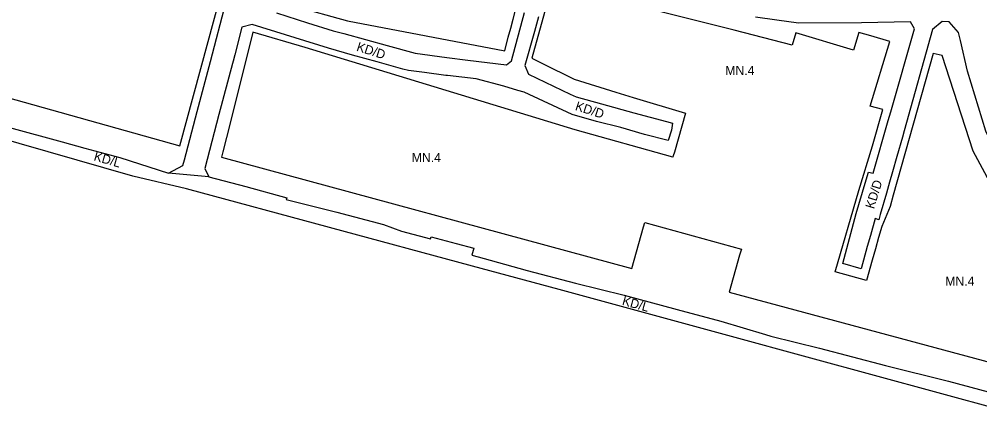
# Model space of a CAD drawing. Extents: x 7417499 to 7419078, y 5548267 to 5548936.
# Drawn here: x 7418035 to 7418562, y 5548333 to 5548556 of the extents above; entities that cross this region are included whole.
import ezdxf

# ---------------------------------------------------------------- set-up
doc = ezdxf.new("R2010")
doc.units = 0
for name, color, linetype in [('linie_rozgraniczajace', 7, 'Continuous'), ('linie_zabudowy_nieprzekraczalne', 7, 'Continuous'), ('oznaczenia_przeznaczen', 7, 'Continuous')]:
    doc.layers.add(name, color=color, linetype=linetype)

msp = doc.modelspace()

# ---------------------------------------------------------------- linework, layer by layer
at = {"layer": 'linie_rozgraniczajace'}
for p, q in [((7418140.18, 5548532.38), (7418148.83, 5548565.16)), ((7418176.38, 5548558.95), (7418193.33, 5548553.59)), ((7418305.05, 5548532.66), (7418312.27, 5548559.22)), ((7418320.01, 5548556.82), (7418317.71, 5548548.86)), ((7418450.55, 5548555.04), (7418438.88, 5548556.71)), ((7418193.33, 5548553.59), (7418207.37, 5548549.17)), ((7418462.43, 5548553.41), (7418450.55, 5548555.04)), ((7418496.94, 5548553.61), (7418462.43, 5548553.41)), ((7418523.79, 5548554.05), (7418496.94, 5548553.61)), ((7418541.11, 5548554.28), (7418535.82, 5548549.91)), ((7418544.87, 5548554.11), (7418541.11, 5548554.28)), ((7418549.91, 5548548.26), (7418544.87, 5548554.11)), ((7418207.37, 5548549.17), (7418213.38, 5548547.69)), ((7418213.38, 5548547.69), (7418236.98, 5548541.18)), ((7418317.71, 5548548.86), (7418312.52, 5548530.15)), ((7418551.14, 5548543.93), (7418549.91, 5548548.26)), ((7418236.98, 5548541.18), (7418252.37, 5548536.92)), ((7418554.84, 5548526.98), (7418551.14, 5548543.93)), ((7418218.11, 5548535.89), (7418204.87, 5548539.59)), ((7418231.55, 5548532.12), (7418218.11, 5548535.89)), ((7418252.37, 5548536.92), (7418269.64, 5548534.56)), ((7418132.97, 5548504.91), (7418140.18, 5548532.38)), ((7418152.36, 5548531.24), (7418144.82, 5548503.35)), ((7418152.67, 5548532.45), (7418152.36, 5548531.24)), ((7418269.64, 5548534.56), (7418281.29, 5548533.12)), ((7418281.29, 5548533.12), (7418302.4, 5548530.51)), ((7418302.4, 5548530.51), (7418305.05, 5548532.66)), ((7418312.52, 5548530.15), (7418314.48, 5548525.43)), ((7418257.44, 5548526.26), (7418248.65, 5548527.34)), ((7418314.48, 5548525.43), (7418337.2, 5548514.42)), ((7418308.63, 5548516.52), (7418300.88, 5548518.75)), ((7418312.08, 5548515.52), (7418308.63, 5548516.52)), ((7418338.39, 5548503.23), (7418312.08, 5548515.52)), ((7418125.98, 5548478.36), (7418132.97, 5548504.91)), ((7418144.82, 5548503.35), (7418137.13, 5548473.69)), ((7418511.48, 5548499.97), (7418512.84, 5548504.75)), ((7418351.66, 5548499.46), (7418338.39, 5548503.23)), ((7418365.02, 5548496.13), (7418351.66, 5548499.46)), ((7418393.36, 5548498.51), (7418392.71, 5548494.63)), ((7418377.94, 5548492.37), (7418365.02, 5548496.13)), ((7418392.71, 5548494.63), (7418391, 5548488.93)), ((7418391, 5548488.93), (7418377.94, 5548492.37)), ((7418519.33, 5548490.87), (7418516.3, 5548480.31)), ((7418516.3, 5548480.31), (7418513.88, 5548471.88)), ((7418137.13, 5548473.69), (7418139.29, 5548469.13)), ((7418513.88, 5548471.88), (7418512.25, 5548466.18)), ((7418127.14, 5548462.45), (7418097.71, 5548469.54)), ((7418139.29, 5548469.13), (7418159.56, 5548463.75)), ((7418159.56, 5548463.75), (7418182.03, 5548457.58)), ((7418512.25, 5548466.18), (7418510.51, 5548460.13)), ((7418182.03, 5548457.58), (7418181.71, 5548456.69)), ((7418510.51, 5548460.13), (7418507.17, 5548448.48)), ((7418506.32, 5548445.51), (7418504.31, 5548446.18)), ((7418507.17, 5548448.48), (7418506.32, 5548445.51)), ((7418235.04, 5548442.95), (7418244.97, 5548439.29)), ((7418244.97, 5548439.29), (7418260.77, 5548435.13)), ((7418260.77, 5548435.13), (7418261.12, 5548436.25)), ((7418284.54, 5548429.93), (7418283.4, 5548426.1)), ((7418500.05, 5548430.86), (7418496.66, 5548418.66)), ((7418283.4, 5548426.1), (7418286.84, 5548425.18)), ((7418286.84, 5548425.18), (7418293.42, 5548423.3)), ((7418293.42, 5548423.3), (7418313.65, 5548417.75)), ((7418313.65, 5548417.75), (7418340.2, 5548410.72)), ((7418340.2, 5548410.72), (7418366.85, 5548404.19)), ((7418469.14, 5548369.7), (7418423.6, 5548382.15)), ((7418473.93, 5548375.07), (7418509.97, 5548365.69)), ((7418603.32, 5548333.1), (7418469.14, 5548369.7)), ((7418509.97, 5548365.69), (7418544.48, 5548357.03)), ((7418544.48, 5548357.03), (7418544.48, 5548357.03)), ((7418544.48, 5548357.03), (7418597.6, 5548342.57))]:
    msp.add_line(p, q, dxfattribs=at)
for points in [[(7418157.51, 5548551.22), (7418153.56, 5548535.92), (7418152.67, 5548532.45)], [(7418204.87, 5548539.59), (7418163.07, 5548552.63), (7418157.51, 5548551.22)], [(7418512.84, 5548504.75), (7418525.89, 5548550.28), (7418523.79, 5548554.05)], [(7418535.82, 5548549.91), (7418520.3, 5548494.35), (7418519.33, 5548490.87)], [(7418248.65, 5548527.34), (7418245.58, 5548528.22), (7418231.55, 5548532.12)], [(7418300.88, 5548518.75), (7418285.78, 5548522.89), (7418269.99, 5548524.6), (7418269.2, 5548524.65), (7418257.44, 5548526.26)], [(7418574.08, 5548474.86), (7418564.97, 5548494.08), (7418554.84, 5548526.98)], [(7418337.2, 5548514.42), (7418340.65, 5548512.9), (7418354.43, 5548509.12), (7418372.2, 5548504.24), (7418389.97, 5548499.35), (7418393.36, 5548498.51)], [(7417998.31, 5548508.7), (7418000.68, 5548504.27), (7418030.07, 5548496.11), (7418059.01, 5548488.22), (7418071.43, 5548484.83), (7418090.51, 5548479.62)], [(7418097.71, 5548469.54), (7417988.86, 5548500.74)], [(7418500.74, 5548471.66), (7418503.19, 5548471.05), (7418511.48, 5548499.97)], [(7418090.51, 5548479.62), (7418117.24, 5548471.13)], [(7418117.24, 5548471.13), (7418125.11, 5548475.33), (7418125.98, 5548478.36)], [(7418139.29, 5548469.13), (7418117.24, 5548471.13)], [(7418139.29, 5548469.13), (7418117.24, 5548471.13)], [(7418493.97, 5548448.92), (7418498.82, 5548465.55), (7418500.74, 5548471.66)], [(7418423.6, 5548382.15), (7418331.2, 5548407.22), (7418283.86, 5548420.06), (7418127.14, 5548462.45)], [(7418181.71, 5548456.69), (7418209.43, 5548449.76), (7418235.04, 5548442.95)], [(7418496.66, 5548418.66), (7418486.56, 5548421.48), (7418493.97, 5548448.92)], [(7418504.31, 5548446.18), (7418501.75, 5548436.93), (7418500.05, 5548430.86)], [(7418261.12, 5548436.25), (7418274.74, 5548432.52), (7418284.54, 5548429.93)], [(7418366.85, 5548404.19), (7418395.81, 5548396.36), (7418419.76, 5548389.88)], [(7418419.76, 5548389.88), (7418444.27, 5548382.61), (7418447.26, 5548381.8), (7418473.93, 5548375.07)]]:
    msp.add_lwpolyline(points, dxfattribs=at)
at = {"layer": 'linie_zabudowy_nieprzekraczalne'}
for points in [[(7418170.45, 5548567.15), (7418178.07, 5548565.03), (7418186.28, 5548562.76), (7418215.34, 5548554.69), (7418301.47, 5548538.23), (7418303.4, 5548545.71), (7418304.77, 5548550.7), (7418306, 5548555.48), (7418312.65, 5548581.26), (7418274.61, 5548597.72), (7418248.17, 5548608.82), (7418213.46, 5548624.57), (7418188.02, 5548636.1), (7418173.89, 5548584.62), (7418172.79, 5548580.63), (7418171.42, 5548575.88), (7418170.72, 5548573.34), (7418169.09, 5548567.49)], [(7418008.07, 5548518.53), (7418123.45, 5548486.07), (7418142.43, 5548556.12), (7418144.75, 5548564.65), (7418073.22, 5548584.12), (7418037.81, 5548593.76)]]:
    msp.add_lwpolyline(points, close=True, dxfattribs=at)
for points in [[(7418585.18, 5548432.48), (7418558.07, 5548483.24), (7418541.02, 5548535.54), (7418536.16, 5548536.81), (7418514.19, 5548459.05), (7418512.58, 5548452.8), (7418507.91, 5548441.83), (7418506.2, 5548435.75), (7418504.47, 5548429.57), (7418502.76, 5548423.46), (7418499.63, 5548412.26), (7418482.41, 5548416.97), (7418495.32, 5548461.6), (7418502.96, 5548486.08), (7418508.47, 5548505.98), (7418501.62, 5548507.9), (7418512.33, 5548543.27), (7418502.03, 5548546.32), (7418495.36, 5548548.29), (7418492.46, 5548538.53), (7418460.86, 5548547.98), (7418458.93, 5548541.34), (7418427.04, 5548549.46), (7418339.67, 5548571.7)], [(7418325.02, 5548565.79), (7418316.21, 5548534.08), (7418322.06, 5548531.18), (7418339.5, 5548522.57), (7418362.29, 5548515.51), (7418371.73, 5548512.68), (7418400.41, 5548504.09), (7418394.38, 5548482.69), (7418393.76, 5548480.55), (7418393.59, 5548479.96), (7418340.01, 5548494.89), (7418192.18, 5548539.93), (7418163.44, 5548548.37), (7418150.95, 5548498.44), (7418146.96, 5548482.8), (7418146.21, 5548479.89), (7418371.04, 5548418.83), (7418377.52, 5548441.66), (7418378.18, 5548444), (7418431.05, 5548429.48), (7418430.09, 5548426.12), (7418424.32, 5548405.88), (7418568.29, 5548367.15)]]:
    msp.add_lwpolyline(points, dxfattribs=at)

# ---------------------------------------------------------------- texts
at = {"layer": 'oznaczenia_przeznaczen'}
for s, rotation, p in [('KD/D', 342.3302, (7418219.88, 5548538.34)), ('KD/D', 342.3302, (7418339.67, 5548505.8)), ('KD/L', 344.1104, (7418075.98, 5548478.18)), ('KD/D', 72.9416, (7418503.65, 5548451.17)), ('KD/L', 344.5217, (7418365.4, 5548398.97))]:
    msp.add_text(s, height=5, rotation=rotation, dxfattribs=at).set_placement(p)
for p in [(7418422.26, 5548524.95), (7418250.5, 5548477.15), (7418542.75, 5548409.38)]:
    msp.add_text('MN.4', height=5, dxfattribs=at).set_placement(p)

doc.saveas('drawing.dxf')
